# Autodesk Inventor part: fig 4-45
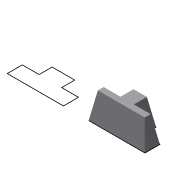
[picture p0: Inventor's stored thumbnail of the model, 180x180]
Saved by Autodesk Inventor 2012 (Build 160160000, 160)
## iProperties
Created: 2004-05
Part Number: fig 4-45
Document SubType Name: Modeling
Designer: CADCIM Technologies
Manufacturer: Standard
Standards Organization: Custom
Density: 1 g/cm^3
Material: Default
Author: CADCIM Technologies
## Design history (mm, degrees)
sketch "Sketch1"
  geometry: L1 (31.783, 34.561)-(31.783, 22.933); L2 (31.783, 22.933)-(16.796, 22.933); L3 (16.796, 22.933)-(16.796, 9.496); L4 (16.796, 9.496)-(66.925, 9.496); L5 (66.925, 9.496)-(66.925, 22.933); L6 (66.925, 22.933)-(51.938, 22.933); L7 (51.938, 22.933)-(51.938, 34.561); L8 (51.938, 34.561)-(31.783, 34.561); L9 (-41.013, 34.561)-(-41.013, 22.933); L10 (-41.013, 22.933)-(-56, 22.933); L11 (-56, 22.933)-(-56, 9.496); L12 (-56, 9.496)-(-5.871, 9.496); L13 (-5.871, 9.496)-(-5.871, 22.933); L14 (-5.871, 22.933)-(-20.858, 22.933); L15 (-20.858, 22.933)-(-20.858, 34.561); L16 (-20.858, 34.561)-(-41.013, 34.561)
  constraints: 32 end point, 10 parallel, 4 equal length, 2 collinear, 2 perpendicular, 2 vertical
extrude "Extrusion1" new body sketch "Sketch1" distance "d0" = 23.25; taper "d1" = -10 deg
body "Solid1"
